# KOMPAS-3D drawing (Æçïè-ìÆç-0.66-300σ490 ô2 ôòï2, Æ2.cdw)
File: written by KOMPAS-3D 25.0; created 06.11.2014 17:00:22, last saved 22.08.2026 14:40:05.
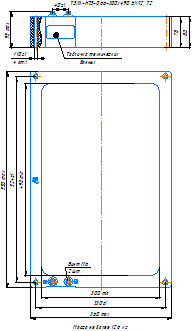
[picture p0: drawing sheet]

Document properties: Утвердил: Альбеков; Автор: LAA; Проверил: Аворник; Форматы листов документа: A4; Полное имя файла: C:\Работа\Извещения 5\ТЗЛК-НТЗ-0,66-300х490\ТЗЛК-НТЗ-0.66-300х490 У2 (УХЛ2, Т2) для ТИ.cdw; Характер работы: М.контр.; Масса: 8.5; Т. контр.: Канканян; Наименование: Трансформатор тока нулевой последовательности ТЗЛК-НТЗ-0,66-100х490 У2 / Габаритный чертеж; Организация: ООО "НТЗ" Волхов"; Н. контр.: Фролова; Количество листов документа: 1; Подписал: Бадулин; Разработал: Хмыров

Views: Вид 1
Referenced files in Y:\Технический отдел\КБ\Рабочая папка\КД\Экспериментальное, тех решения\ТЗЛК-0.66-100х490\: Трансформатор тока нулевой последовательности ТЗЛК-НТЗ-0,66-100х490 У2 Габаритный чертеж НТЗ.03.05.00.00.000 ГЧ.cdw
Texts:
  Как сохранено
  По умолчанию
  max
  min
  Табличка технических
  данных
  Масса не более 12,6 кг
  Винт М6
  ТЗЛК-НТЗ-0,66-300х490 УХЛ2, Т2
  Трансформатор тока
  нулевой последовательности
  ТЗЛК-НТЗ-0,66-100х490 У2
  Габаритный чертеж
  Хмыров
  Аворник
  Канканян
  Фролова
  Альбеков
  НТЗ
  НТЗ.03.0.5.00.00.000
  М.контр.
  Бадулин
  Без оформления
Dimensions and other numbers on the sheet: 550; 360; 300; 490; 330±1; 524±1; 40±1; 78; 95; 80; 2 шт.; 10; 4 отв.; 1:2; 1; 8,5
